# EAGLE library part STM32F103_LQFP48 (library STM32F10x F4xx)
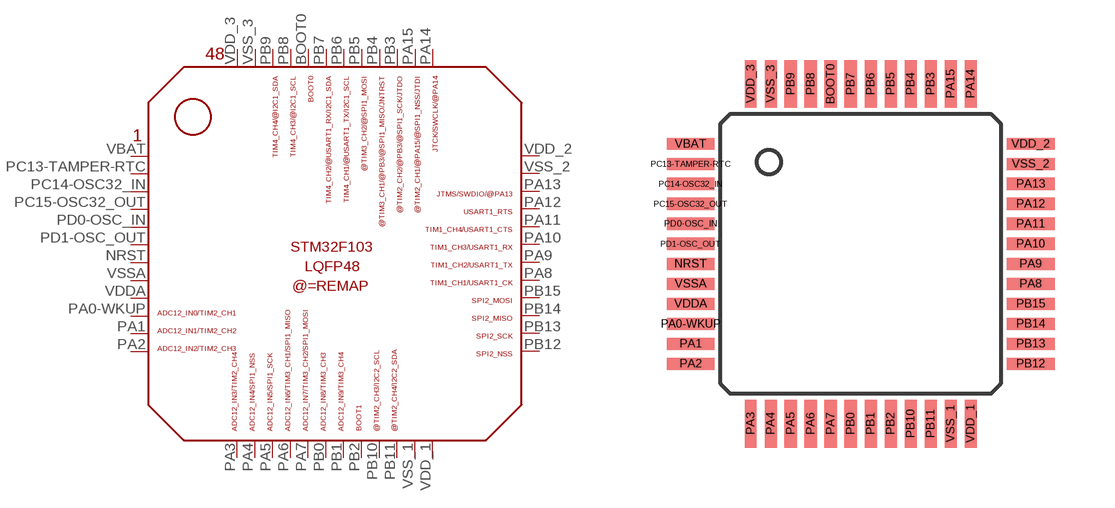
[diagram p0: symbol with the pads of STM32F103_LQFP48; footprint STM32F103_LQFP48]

Designator prefix -

## STM32F103_LQFP48  [STM32F103_LQFP48]
BOOT0  BOOT0
NRST  NRST
PA0-WKUP  PA0-WKUP
PA1  PA1
PA2  PA2
PA3  PA3
PA4  PA4
PA5  PA5
PA6  PA6
PA7  PA7
PA8  PA8
PA9  PA9
PA10  PA10
PA11  PA11
PA12  PA12
PA13  PA13
PA14  PA14
PA15  PA15
PB0  PB0
PB1  PB1
PB2  PB2
PB3  PB3
PB4  PB4
PB5  PB5
PB6  PB6
PB7  PB7
PB8  PB8
PB9  PB9
PB10  PB10
PB11  PB11
PB12  PB12
PB13  PB13
PB14  PB14
PB15  PB15
PC13-TAMPER-RTC  PC13-TAMPER-RTC
PC14-OSC32_IN  PC14-OSC32_IN
PC15-OSC32_OUT  PC15-OSC_OUT
PD0-OSC_IN  PD0-OSC_IN
PD1-OSC_OUT  PD1-OSC_OUT
VBAT  VBAT
VDD_1  VDD_1
VDD_2  VDD_2
VDD_3  VDD_3
VDDA  VDDA
VSS_1  VSS_1
VSS_2  VSS_2
VSS_3  VSS_3
VSSA  VSSA

## Footprint STM32F103_LQFP48 (pad centres in mm)
smd 0.3 x 1.2: BOOT0 -0.75,4.25; PA3 -2.75,-4.25; PA4 -2.25,-4.25; PA5 -1.75,-4.25; PA6 -1.25,-4.25; PA7 -0.75,-4.25; PA14 2.75,4.25; PA15 2.25,4.25; PB0 -0.25,-4.25; PB1 0.25,-4.25; PB2 0.75,-4.25; PB3 1.75,4.25; PB4 1.25,4.25; PB5 0.75,4.25; PB6 0.25,4.25; PB7 -0.25,4.25; PB8 -1.25,4.25; PB9 -1.75,4.25; PB10 1.25,-4.25; PB11 1.75,-4.25; VDD_1 2.75,-4.25; VDD_3 -2.75,4.25; VSS_1 2.25,-4.25; VSS_3 -2.25,4.25
smd 1.2 x 0.3: NRST -4.25,-0.25; PA0-WKUP -4.25,-1.75; PA1 -4.25,-2.25; PA2 -4.25,-2.75; PA8 4.25,-0.75; PA9 4.25,-0.25; PA10 4.25,0.25; PA11 4.25,0.75; PA12 4.25,1.25; PA13 4.25,1.75; PB12 4.25,-2.75; PB13 4.25,-2.25; PB14 4.25,-1.75; PB15 4.25,-1.25; PC13-TAMPER-RTC -4.25,2.25; PC14-OSC32_IN -4.25,1.75; PC15-OSC32_OUT -4.25,1.25; PD0-OSC_IN -4.25,0.75; PD1-OSC_OUT -4.25,0.25; VBAT -4.25,2.75; VDD_2 4.25,2.75; VDDA -4.25,-1.25; VSS_2 4.25,2.25; VSSA -4.25,-0.75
